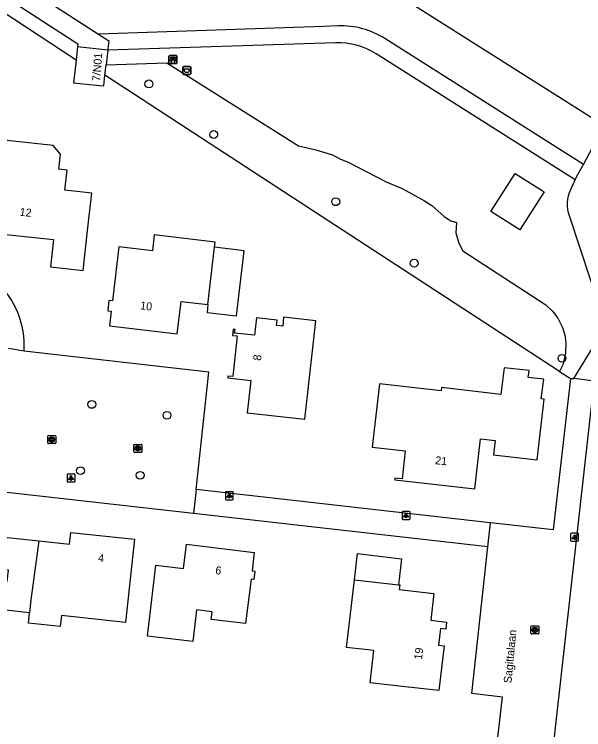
# Model space of a CAD drawing. Extents: x 162398 to 163643, y 386453 to 387397.
# Drawn here: x 163024.9 to 163096.1, y 386594.8 to 386684.2 of the extents above; entities that cross this region are included whole.
import ezdxf

# ---------------------------------------------------------------- set-up
doc = ezdxf.new("R2010")
doc.units = 0
for name, color, linetype in [('IMGEO_Afvalbak', 7, 'Continuous'), ('IMGEO_Bank', 7, 'Continuous'), ('IMGEO_Boom', 7, 'Continuous'), ('IMGEO_Groenvoorziening', 7, 'Continuous'), ('IMGEO_Kolk', 7, 'Continuous'), ('IMGEO_Lichtpunt', 7, 'Continuous'), ('IMGEO_Openbare_ruimte_label', 7, 'Continuous'), ('IMGEO_Pand', 7, 'Continuous'), ('IMGEO_Pand_nummerreeks', 7, 'Continuous'), ('IMGEO_Parkeervlak_open', 7, 'Continuous'), ('IMGEO_Voetpad_halfverhard', 7, 'Continuous'), ('IMGEO_Voetpad_open', 7, 'Continuous')]:
    doc.layers.add(name, color=color, linetype=linetype)

msp = doc.modelspace()

# ---------------------------------------------------------------- linework, layer by layer
at = {"layer": 'IMGEO_Afvalbak'}
for p, q in [((163045.992, 386676.806), (163045.992, 386677.606)), ((163045.992, 386677.606), (163045.992, 386676.806)), ((163046.092, 386677.706), (163046.882, 386677.706)), ((163046.882, 386677.706), (163046.092, 386677.706)), ((163046.982, 386677.606), (163046.982, 386676.806)), ((163046.982, 386676.806), (163046.982, 386677.606)), ((163046.882, 386676.706), (163046.092, 386676.706)), ((163046.092, 386676.706), (163046.882, 386676.706))]:
    msp.add_line(p, q, dxfattribs=at)
msp.add_lwpolyline([(163046.135, 386677.42), (163046.839, 386677.42), (163046.69, 386676.95), (163046.284, 386676.95), (163046.135, 386677.42)], dxfattribs=at)
for centre, start, end in [((163046.092, 386677.606), 90, 180), ((163046.092, 386677.606), 90, 180), ((163046.882, 386677.606), 0, 90), ((163046.882, 386677.606), 360, 90), ((163046.092, 386676.806), 180, 270), ((163046.092, 386676.806), 180, 270), ((163046.882, 386676.806), 270, 0), ((163046.882, 386676.806), 270, 0)]:
    msp.add_arc(centre, 0.1, start, end, dxfattribs=at)
at = {"layer": 'IMGEO_Bank'}
for p, q in [((163044.267, 386678.15), (163044.267, 386678.991)), ((163044.267, 386678.991), (163044.267, 386678.15)), ((163044.342, 386679.075), (163045.183, 386679.075)), ((163045.183, 386679.075), (163044.342, 386679.075)), ((163044.576, 386678.581), (163044.576, 386678.687)), ((163044.62, 386678.687), (163044.62, 386678.581)), ((163044.908, 386678.693), (163044.626, 386678.693)), ((163044.914, 386678.581), (163044.914, 386678.687)), ((163044.958, 386678.687), (163044.958, 386678.581)), ((163045.267, 386679), (163045.267, 386678.159)), ((163045.267, 386678.159), (163045.267, 386679)), ((163045.192, 386678.075), (163044.351, 386678.075)), ((163044.351, 386678.075), (163045.192, 386678.075)), ((163044.964, 386678.473), (163044.571, 386678.473)), ((163044.626, 386678.575), (163044.908, 386678.575))]:
    msp.add_line(p, q, dxfattribs=at)
for points in [[(163044.57, 386678.693), (163044.484, 386678.693), (163044.484, 386678.854), (163045.047, 386678.854), (163045.047, 386678.693), (163044.964, 386678.693)], [(163044.514, 386678.473), (163044.372, 386678.473), (163044.484, 386678.575), (163044.57, 386678.575)], [(163044.564, 386678.466), (163044.564, 386678.259), (163044.521, 386678.259), (163044.521, 386678.466)], [(163044.964, 386678.575), (163045.047, 386678.575), (163045.159, 386678.473), (163045.02, 386678.473)], [(163045.014, 386678.466), (163045.014, 386678.259), (163044.97, 386678.259), (163044.97, 386678.466)]]:
    msp.add_lwpolyline(points, dxfattribs=at)
for centre, radius, start, end in [((163044.345, 386678.997), 0.0779, 92.4484, 184.28452), ((163044.345, 386678.997), 0.0779, 92.4484, 184.28452), ((163044.569, 386678.686), 0.00671, 2.89567, 87.10433), ((163044.626, 386678.686), 0.00671, 92.89567, 177.10433), ((163044.908, 386678.686), 0.00671, 2.89567, 87.10433), ((163044.965, 386678.686), 0.00671, 92.89567, 177.10433), ((163045.189, 386678.997), 0.0779, 2.4484, 94.28452), ((163045.189, 386678.997), 0.0779, 2.4484, 94.28452), ((163044.345, 386678.153), 0.0779, 182.4484, 274.28452), ((163044.345, 386678.153), 0.0779, 182.4484, 274.28452), ((163044.514, 386678.466), 0.00671, 2.89567, 87.10433), ((163044.571, 386678.466), 0.00671, 92.89567, 177.10433), ((163044.569, 386678.582), 0.00671, 272.89567, 357.10433), ((163044.626, 386678.582), 0.00671, 182.89567, 267.10433), ((163044.908, 386678.582), 0.00671, 272.89567, 357.10433), ((163044.965, 386678.582), 0.00671, 182.89567, 267.10433), ((163044.963, 386678.466), 0.00671, 2.89567, 87.10433), ((163045.02, 386678.466), 0.00671, 92.89567, 177.10433), ((163045.189, 386678.153), 0.0779, 272.4484, 4.28452), ((163045.189, 386678.153), 0.0779, 272.4484, 4.28452)]:
    msp.add_arc(centre, radius, start, end, dxfattribs=at)
at = {"layer": 'IMGEO_Boom'}
for centre in [(163041.757, 386675.528), (163049.864, 386669.2), (163065.119, 386660.805), (163074.922, 386653.122), (163093.406, 386641.242), (163034.616, 386635.482), (163044.012, 386634.117), (163033.21, 386627.2), (163040.664, 386626.624)]:
    msp.add_circle(centre, 0.489, dxfattribs=at)
at = {"layer": 'IMGEO_Groenvoorziening'}
for points in [[(163097.834, 386670.816), (163026.239, 386716.082)], [(163032.648, 386678.484), (163000, 386699.965), (162997.926, 386701.329)], [(163036.406, 386677.912), (163044, 386678.16), (163060.463, 386667.784), (163062.612, 386667.298), (163064.732, 386666.671), (163065.695, 386666.141), (163066.659, 386665.755), (163071.428, 386663.296), (163073.403, 386662.477), (163076.198, 386660.934), (163077.113, 386660.355), (163078.655, 386658.957), (163079.522, 386658.427), (163080.198, 386658.221), (163080.135, 386656.909), (163080.515, 386655.639), (163081.022, 386654.66), (163091.38, 386647.928), (163092.214, 386647.137), (163092.876, 386646.263), (163093.455, 386645.105), (163093.741, 386644.192), (163093.889, 386643.156), (163093.845, 386641.889), (163093.497, 386640.443), (163093.106, 386639.582)], [(163093.106, 386639.582), (163036.266, 386676.636)], [(163087.531, 386664.343), (163091.158, 386662.022), (163088.123, 386657.279), (163084.496, 386659.6), (163087.531, 386664.343)], [(163093.106, 386639.582), (163094.455, 386638.702)]]:
    msp.add_lwpolyline(points, dxfattribs=at)
at = {"layer": 'IMGEO_Kolk'}
for p, q in [((163029.108, 386630.664), (163029.108, 386631.516)), ((163029.183, 386631.59), (163030.035, 386631.59)), ((163029.596, 386631.37), (163029.621, 386631.37)), ((163030.109, 386631.516), (163030.109, 386630.664)), ((163030.035, 386630.59), (163029.183, 386630.59)), ((163029.619, 386630.81), (163029.594, 386630.81)), ((163039.876, 386629.564), (163039.876, 386630.416)), ((163039.951, 386630.49), (163040.803, 386630.49)), ((163040.877, 386630.416), (163040.877, 386629.564)), ((163040.387, 386629.71), (163040.362, 386629.71)), ((163040.364, 386630.27), (163040.389, 386630.27)), ((163040.803, 386629.49), (163039.951, 386629.49)), ((163089.508, 386606.885), (163089.508, 386607.737)), ((163089.583, 386607.811), (163090.435, 386607.811)), ((163089.996, 386607.591), (163090.021, 386607.591)), ((163090.509, 386607.737), (163090.509, 386606.885)), ((163090.435, 386606.811), (163089.583, 386606.811)), ((163090.019, 386607.031), (163089.994, 386607.031))]:
    msp.add_line(p, q, dxfattribs=at)
for points in [[(163029.108, 386630.664), (163029.108, 386631.516)], [(163029.183, 386631.59), (163030.035, 386631.59)], [(163030.109, 386631.516), (163030.109, 386630.664)], [(163030.035, 386630.59), (163029.183, 386630.59)], [(163029.429, 386631.29), (163029.552, 386631.29), (163029.552, 386631.139), (163029.682, 386631.29), (163029.846, 386631.29), (163029.7, 386631.139), (163029.853, 386630.89), (163029.701, 386630.89), (163029.616, 386631.054), (163029.552, 386630.987), (163029.552, 386630.89), (163029.429, 386630.89), (163029.429, 386631.29)], [(163039.876, 386629.564), (163039.876, 386630.416)], [(163039.951, 386630.49), (163040.803, 386630.49)], [(163040.877, 386630.416), (163040.877, 386629.564)], [(163040.197, 386630.19), (163040.32, 386630.19), (163040.32, 386630.039), (163040.45, 386630.19), (163040.614, 386630.19), (163040.468, 386630.039), (163040.621, 386629.79), (163040.469, 386629.79), (163040.384, 386629.954), (163040.32, 386629.887), (163040.32, 386629.79), (163040.197, 386629.79), (163040.197, 386630.19)], [(163040.803, 386629.49), (163039.951, 386629.49)], [(163089.508, 386606.885), (163089.508, 386607.737)], [(163089.583, 386607.811), (163090.435, 386607.811)], [(163089.829, 386607.511), (163089.952, 386607.511), (163089.952, 386607.36), (163090.082, 386607.511), (163090.246, 386607.511), (163090.1, 386607.36), (163090.253, 386607.111), (163090.101, 386607.111), (163090.016, 386607.275), (163089.952, 386607.208), (163089.952, 386607.111), (163089.829, 386607.111), (163089.829, 386607.511)], [(163090.509, 386607.737), (163090.509, 386606.885)], [(163090.435, 386606.811), (163089.583, 386606.811)]]:
    msp.add_lwpolyline(points, dxfattribs=at)
for centre, start, end in [((163029.185, 386631.514), 91.55205, 178.44795), ((163029.185, 386631.514), 91.55205, 178.44795), ((163030.033, 386631.514), 1.55205, 88.44795), ((163030.033, 386631.514), 1.55205, 88.44795), ((163029.185, 386630.666), 181.55205, 268.44795), ((163029.185, 386630.666), 181.55205, 268.44795), ((163030.033, 386630.666), 271.55205, 358.44795), ((163030.033, 386630.666), 271.55205, 358.44795), ((163039.953, 386630.414), 91.55205, 178.44795), ((163039.953, 386630.414), 91.55205, 178.44795), ((163040.801, 386630.414), 1.55205, 88.44795), ((163040.801, 386630.414), 1.55205, 88.44795), ((163039.953, 386629.566), 181.55205, 268.44795), ((163039.953, 386629.566), 181.55205, 268.44795), ((163040.801, 386629.566), 271.55205, 358.44795), ((163040.801, 386629.566), 271.55205, 358.44795), ((163089.585, 386607.735), 91.55205, 178.44795), ((163089.585, 386607.735), 91.55205, 178.44795), ((163090.433, 386607.735), 1.55205, 88.44795), ((163090.433, 386607.735), 1.55205, 88.44795), ((163089.585, 386606.887), 181.55205, 268.44795), ((163089.585, 386606.887), 181.55205, 268.44795), ((163090.433, 386606.887), 271.55205, 358.44795), ((163090.433, 386606.887), 271.55205, 358.44795)]:
    msp.add_arc(centre, 0.0765, start, end, dxfattribs=at)
for centre, major_axis, ratio, start_param, end_param in [((163029.595, 386631.09), (-0.387, 0.002), 0.722429, 4.712389, 7.853982), ((163029.62, 386631.09), (-0.39, 0.002), 0.717154, 1.570796, 4.712389), ((163040.363, 386629.99), (-0.387, 0.002), 0.722429, 4.712389, 7.853982), ((163040.388, 386629.99), (-0.39, 0.002), 0.717154, 1.570796, 4.712389), ((163089.995, 386607.311), (-0.387, 0.002), 0.722429, 4.712389, 7.853982), ((163090.02, 386607.311), (-0.39, 0.002), 0.717154, 1.570796, 4.712389)]:
    msp.add_ellipse(centre, major_axis=major_axis, ratio=ratio, start_param=start_param, end_param=end_param, dxfattribs=at)
at = {"layer": 'IMGEO_Lichtpunt'}
for p, q in [((163031.53, 386626.689), (163031.53, 386625.882)), ((163031.53, 386626.689), (163031.53, 386625.882)), ((163032.432, 386626.784), (163031.624, 386626.784)), ((163032.432, 386626.784), (163031.624, 386626.784)), ((163032.526, 386625.882), (163032.526, 386626.689)), ((163032.526, 386625.882), (163032.526, 386626.689)), ((163031.624, 386625.788), (163032.432, 386625.788)), ((163031.624, 386625.788), (163032.432, 386625.788)), ((163051.314, 386624.479), (163051.314, 386623.672)), ((163051.314, 386624.479), (163051.314, 386623.672)), ((163052.216, 386624.574), (163051.408, 386624.574)), ((163052.216, 386624.574), (163051.408, 386624.574)), ((163052.31, 386623.672), (163052.31, 386624.479)), ((163052.31, 386623.672), (163052.31, 386624.479)), ((163051.408, 386623.578), (163052.216, 386623.578)), ((163051.408, 386623.578), (163052.216, 386623.578)), ((163073.408, 386622.012), (163073.408, 386621.205)), ((163073.408, 386622.012), (163073.408, 386621.205)), ((163074.31, 386622.107), (163073.502, 386622.107)), ((163074.31, 386622.107), (163073.502, 386622.107)), ((163074.404, 386621.205), (163074.404, 386622.012)), ((163074.404, 386621.205), (163074.404, 386622.012)), ((163073.502, 386621.111), (163074.31, 386621.111)), ((163073.502, 386621.111), (163074.31, 386621.111)), ((163094.486, 386619.292), (163094.486, 386618.485)), ((163094.486, 386619.292), (163094.486, 386618.485)), ((163095.388, 386619.387), (163094.58, 386619.387)), ((163095.388, 386619.387), (163094.58, 386619.387)), ((163095.482, 386618.485), (163095.482, 386619.292)), ((163095.482, 386618.485), (163095.482, 386619.292)), ((163094.58, 386618.391), (163095.388, 386618.391)), ((163094.58, 386618.391), (163095.388, 386618.391))]:
    msp.add_line(p, q, dxfattribs=at)
for points in [[(163031.904, 386626.353), (163031.943, 386626.325), (163031.755, 386626.063), (163031.717, 386626.09), (163031.904, 386626.353)], [(163032.006, 386626.305), (163032.053, 386626.305), (163032.053, 386625.983), (163032.006, 386625.983), (163032.006, 386626.305)], [(163032.116, 386626.325), (163032.154, 386626.352), (163032.341, 386626.09), (163032.302, 386626.062), (163032.116, 386626.325)], [(163051.688, 386624.143), (163051.727, 386624.115), (163051.539, 386623.853), (163051.501, 386623.88), (163051.688, 386624.143)], [(163051.79, 386624.095), (163051.837, 386624.095), (163051.837, 386623.773), (163051.79, 386623.773), (163051.79, 386624.095)], [(163051.9, 386624.115), (163051.938, 386624.142), (163052.125, 386623.88), (163052.086, 386623.852), (163051.9, 386624.115)], [(163073.782, 386621.676), (163073.821, 386621.648), (163073.633, 386621.386), (163073.595, 386621.413), (163073.782, 386621.676)], [(163073.884, 386621.628), (163073.931, 386621.628), (163073.931, 386621.306), (163073.884, 386621.306), (163073.884, 386621.628)], [(163073.994, 386621.648), (163074.032, 386621.675), (163074.219, 386621.413), (163074.18, 386621.385), (163073.994, 386621.648)], [(163094.86, 386618.956), (163094.899, 386618.928), (163094.711, 386618.666), (163094.673, 386618.693), (163094.86, 386618.956)], [(163094.962, 386618.908), (163095.009, 386618.908), (163095.009, 386618.586), (163094.962, 386618.586), (163094.962, 386618.908)], [(163095.072, 386618.928), (163095.11, 386618.955), (163095.297, 386618.693), (163095.258, 386618.665), (163095.072, 386618.928)]]:
    msp.add_lwpolyline(points, dxfattribs=at)
for centre in [(163032.029, 386626.487), (163051.813, 386624.277), (163073.907, 386621.81), (163094.985, 386619.09)]:
    msp.add_circle(centre, 0.0994, dxfattribs=at)
for centre, start, end in [((163031.624, 386626.689), 90, 180), ((163031.624, 386626.689), 90, 180), ((163032.432, 386626.689), 0, 90), ((163032.432, 386626.689), 0, 90), ((163031.624, 386625.882), 180, 270), ((163031.624, 386625.882), 180, 270), ((163032.432, 386625.882), 270, 0), ((163032.432, 386625.882), 270, 360), ((163051.408, 386624.479), 90, 180), ((163051.408, 386624.479), 90, 180), ((163052.216, 386624.479), 0, 90), ((163052.216, 386624.479), 0, 90), ((163051.408, 386623.672), 180, 270), ((163051.408, 386623.672), 180, 270), ((163052.216, 386623.672), 270, 0), ((163052.216, 386623.672), 270, 360), ((163073.502, 386622.012), 90, 180), ((163073.502, 386622.012), 90, 180), ((163074.31, 386622.012), 0, 90), ((163074.31, 386622.012), 0, 90), ((163073.502, 386621.205), 180, 270), ((163073.502, 386621.205), 180, 270), ((163074.31, 386621.205), 270, 0), ((163074.31, 386621.205), 270, 360), ((163094.58, 386619.292), 90, 180), ((163094.58, 386619.292), 90, 180), ((163095.388, 386619.292), 0, 90), ((163095.388, 386619.292), 0, 90), ((163094.58, 386618.485), 180, 270), ((163094.58, 386618.485), 180, 270), ((163095.388, 386618.485), 270, 0), ((163095.388, 386618.485), 270, 360)]:
    msp.add_arc(centre, 0.0946, start, end, dxfattribs=at)
at = {"layer": 'IMGEO_Pand'}
for points in [[(163032.831, 386680.161), (163032.648, 386678.484)], [(163036.607, 386679.749), (163032.831, 386680.161)], [(163036.607, 386679.749), (163036.406, 386677.912)], [(163032.648, 386678.484), (163032.491, 386677.049), (163032.341, 386675.674), (163034.772, 386675.408), (163036.105, 386675.273), (163036.266, 386676.636)], [(163036.266, 386676.636), (163036.406, 386677.912)], [(163030.509, 386664.873), (163030.714, 386666.764), (163029.775, 386667.816), (163022.469, 386668.607), (163022.162, 386665.776), (163023.181, 386665.666), (163022.769, 386661.864), (163022.231, 386656.893), (163029.811, 386656.072), (163029.442, 386652.665), (163033.555, 386652.22), (163034.094, 386657.191), (163034.602, 386661.885), (163031.249, 386662.248), (163031.522, 386664.763), (163030.509, 386664.873)], [(163049.957, 386655.119), (163050.034, 386655.769), (163042.434, 386656.664), (163042.198, 386654.661), (163038.006, 386655.155), (163037.212, 386648.411), (163036.755, 386648.465), (163036.604, 386647.186), (163037.042, 386647.135), (163036.824, 386645.281), (163045.291, 386644.284), (163045.77, 386648.352), (163049.142, 386647.955)], [(163049.142, 386647.955), (163049.026, 386646.971), (163052.721, 386646.536), (163053.68, 386654.681), (163049.957, 386655.119)], [(163049.142, 386647.955), (163049.957, 386655.119)], [(163062.327, 386643.31), (163062.615, 386645.93), (163058.604, 386646.371), (163058.482, 386645.271), (163057.711, 386645.356), (163057.784, 386646.017), (163055.21, 386646.3), (163054.97, 386644.12), (163052.479, 386644.394), (163052.53, 386644.858), (163052.303, 386644.883), (163052.217, 386644.101), (163052.811, 386644.036), (163052.252, 386638.956), (163051.634, 386639.024), (163051.608, 386638.787), (163054.482, 386638.47), (163054.038, 386634.44), (163061.263, 386633.645), (163062.327, 386643.31)], [(163091.158, 386636.124), (163090.796, 386636.165), (163091.14, 386638.622), (163089.196, 386638.843), (163089.297, 386639.698), (163086.17, 386640.053), (163085.778, 386636.735), (163078.34, 386637.579), (163078.297, 386637.196), (163070.58, 386638.071), (163069.68, 386630.14), (163073.8, 386629.673), (163073.404, 386626.182), (163072.516, 386626.283), (163072.491, 386626.061), (163082.488, 386624.926), (163083.198, 386631.174), (163085.036, 386630.965), (163084.833, 386629.179), (163090.298, 386628.558), (163091.158, 386636.124)], [(163026.833, 386609.438), (163023.863, 386609.759), (163023.116, 386602.852), (163017.494, 386603.46), (163012.522, 386603.997), (163013.01, 386608.517), (163014.544, 386608.351), (163014.591, 386608.783), (163015.958, 386608.635), (163016.556, 386614.165), (163024.05, 386613.355), (163024.202, 386614.764), (163021.21, 386615.088), (163021.646, 386619.122), (163027.975, 386618.438)], [(163027.975, 386618.438), (163031.846, 386618.019), (163032.005, 386619.49), (163039.963, 386618.63), (163039.426, 386613.659), (163038.838, 386608.225), (163030.817, 386609.092), (163030.669, 386607.725), (163026.695, 386608.155), (163026.833, 386609.438)], [(163027.975, 386618.438), (163027.01, 386611.079), (163026.833, 386609.438)], [(163041.568, 386606.544), (163042.036, 386610.412), (163042.636, 386615.375), (163046.068, 386614.96), (163046.439, 386618.023), (163054.93, 386616.996), (163054.649, 386614.672), (163054.99, 386614.63), (163054.867, 386613.61), (163054.523, 386613.652), (163053.85, 386608.086), (163049.545, 386608.607), (163049.661, 386609.565), (163047.723, 386609.799), (163047.246, 386605.857), (163041.568, 386606.544)], [(163067.461, 386613.581), (163067.839, 386616.842), (163073.328, 386616.204), (163072.95, 386612.944)], [(163072.95, 386612.944), (163073.121, 386612.924), (163073.054, 386612.352), (163077.385, 386611.849), (163076.997, 386608.508), (163078.976, 386608.278), (163078.876, 386607.417), (163078.208, 386607.494), (163077.965, 386605.4), (163078.657, 386605.32), (163078.006, 386599.716), (163073.04, 386600.292), (163069.417, 386600.713), (163069.882, 386604.718), (163066.479, 386605.113), (163066.885, 386608.615), (163067.461, 386613.581)], [(163067.461, 386613.581), (163072.95, 386612.944)]]:
    msp.add_lwpolyline(points, dxfattribs=at)
at = {"layer": 'IMGEO_Parkeervlak_open'}
for points in [[(163047.656, 386624.851), (163049.253, 386639.503), (163026.16, 386642.139)], [(163047.319, 386621.839), (163018.036, 386625.127)]]:
    msp.add_lwpolyline(points, dxfattribs=at)
at = {"layer": 'IMGEO_Voetpad_halfverhard'}
for points in [[(163065.406, 386682.78), (163063.605, 386682.718), (163035.465, 386681.75)], [(163065.071, 386680.664), (163036.607, 386679.749)], [(163096.099, 386665.463), (163071.256, 386681.192)], [(163095.05, 386663.524), (163070.175, 386679.273)], [(163096.099, 386665.463), (163098.658, 386670.324)], [(163095.05, 386663.524), (163095.228, 386663.914), (163096.099, 386665.463)], [(163094.885, 386638.711), (163097.938, 386643.666), (163098.108, 386643.971), (163098.249, 386644.291), (163098.362, 386644.621), (163098.444, 386644.96), (163098.496, 386645.306), (163098.517, 386645.654), (163098.506, 386646.003), (163098.465, 386646.35), (163098.393, 386646.692), (163098.325, 386646.923), (163094.325, 386659.047), (163094.224, 386659.421), (163094.147, 386659.844), (163094.109, 386660.271), (163094.109, 386660.701), (163094.147, 386661.128), (163094.223, 386661.551), (163094.337, 386661.965), (163094.638, 386662.623), (163095.05, 386663.524)]]:
    msp.add_lwpolyline(points, dxfattribs=at)
for centre, radius, start, end in [((163065.758, 386672.508), 10.278, 57.66233, 91.96339), ((163065.36, 386671.666), 9.003, 57.66881, 91.84186)]:
    msp.add_arc(centre, radius, start, end, dxfattribs=at)
at = {"layer": 'IMGEO_Voetpad_open'}
for points in [[(163000.29, 386704.411), (163035.465, 386681.75)], [(162998.844, 386702.561), (163000, 386701.813), (163032.875, 386680.532), (163032.831, 386680.161)], [(163035.465, 386681.75), (163036.736, 386680.928), (163036.63, 386679.921), (163036.607, 386679.749)], [(163026.16, 386642.139), (163024.192, 386642.451)], [(163094.455, 386638.702), (163092.306, 386619.818), (163084.452, 386620.703)], [(163094.455, 386638.702), (163094.885, 386638.711)], [(163097.523, 386638.37), (163094.885, 386638.711)], [(163090.42, 386575.726), (163097.29, 386637.077)], [(163047.656, 386624.851), (163047.319, 386621.839)], [(163084.452, 386620.703), (163084.437, 386620.705), (163047.656, 386624.851)], [(163084.149, 386617.704), (163047.319, 386621.839)], [(163084.149, 386617.704), (163084.452, 386620.703)], [(163078.11, 386572.372), (163082.937, 386572.643), (163085.957, 386598.897), (163082.131, 386599.35), (163084.149, 386617.704)]]:
    msp.add_lwpolyline(points, dxfattribs=at)
msp.add_arc((163014.999, 386642.756), 11.178, 356.83783, 47.19234, dxfattribs=at)

# ---------------------------------------------------------------- texts
at = {"layer": 'IMGEO_Openbare_ruimte_label'}
msp.add_text('Sagittalaan', height=1, rotation=84.60854, dxfattribs=at).set_placement((163087.09, 386600.615))
at = {"layer": 'IMGEO_Pand_nummerreeks'}
for s, rotation, p in [('7/N01', 85.59989, (163035.66, 386675.825)), ('12', 353.81831, (163025.558, 386659.068)), ('10', 353.28427, (163040.625, 386647.372)), ('8', 83.72059, (163055.768, 386640.907)), ('21', 353.52558, (163077.509, 386628.028)), ('4', 353.83497, (163035.357, 386615.829)), ('6', 353.10348, (163050.017, 386614.286)), ('19', 83.53725, (163075.904, 386603.55))]:
    msp.add_text(s, height=1, rotation=rotation, dxfattribs=at).set_placement(p)

doc.saveas('drawing.dxf')
